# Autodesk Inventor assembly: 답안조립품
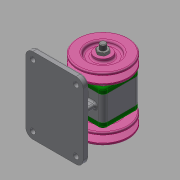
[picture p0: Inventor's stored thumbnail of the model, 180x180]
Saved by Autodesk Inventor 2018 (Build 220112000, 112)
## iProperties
Created: 2020-11
Part Number: 답안조립품
Document SubType Name: Assembly
Designer: 1-16
Author: 1-16
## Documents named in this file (10)
- C:\Users\1-16\Desktop\701106V1051\답안조립품.iam
- C:\Users\1-16\Desktop\701106V1051\본체.ipt
- C:\Users\1-16\Desktop\701106V1051\축.ipt
- C:\Users\1-16\Desktop\701106V1051\베어링 6004.ipt
- C:\Users\1-16\Desktop\701106V1051\커버.ipt
- C:\Users\1-16\Desktop\701106V1051\오일 실 17 30 5.ipt
- C:\Users\1-16\Desktop\701106V1051\키 5 x 5 x 12.ipt
- C:\Users\1-16\Desktop\701106V1051\V-벨트풀리.ipt
- C:\Users\1-16\Desktop\701106V1051\너트 M10x1.ipt
- C:\Users\1-16\Desktop\701106V1051\볼트 M4.ipt
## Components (2 placed, 1 different names)
1. V-벨트풀리:1
2. V-벨트풀리:2
